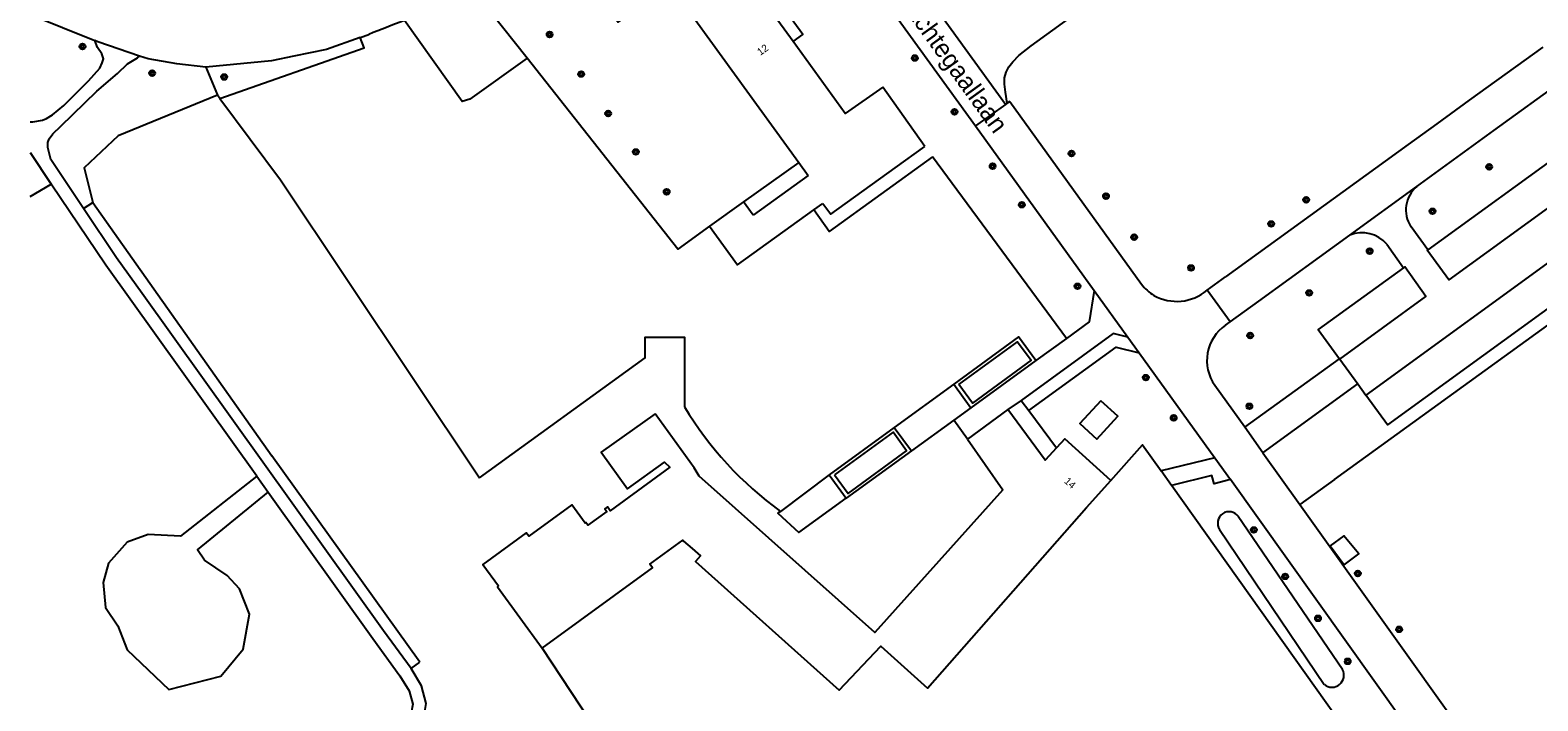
# Model space of a CAD drawing. Extents: x 141000 to 143000, y 400580 to 403500.
# Drawn here: x 141000 to 141206, y 402672.1 to 402763.7 of the extents above; entities that cross this region are included whole.
import ezdxf

# ---------------------------------------------------------------- set-up
doc = ezdxf.new("R2010")
doc.units = 0
for name, color, linetype in [('gg-afsc-erfafscheiding', 7, 'Continuous'), ('gg-afsc-hekwerk', 7, 'Continuous'), ('gg-anno-huisnummerreeks BGT', 7, 'Continuous'), ('gg-anno-openbare ruimte label', 7, 'Continuous'), ('gg-bbg-bijgebouw', 7, 'Continuous'), ('gg-bbg-gedigitaliseerde bebouwing', 7, 'Continuous'), ('gg-bbg-gedigitaliseerde bijgebouw', 7, 'Continuous'), ('gg-bbg-hoofdgebouw', 7, 'Continuous'), ('gg-bbg-luifel en loopbrug', 7, 'Continuous'), ('gg-knt-bronhoudergrens', 7, 'Continuous'), ('gg-knt-onverhard', 7, 'Continuous'), ('gg-knt-verharding', 7, 'Continuous'), ('gg-knt-verharding nz', 7, 'Continuous'), ('gg-kntw-bovenkant insteek waterloop', 7, 'Continuous'), ('gt-grn-groengrens', 7, 'Continuous'), ('gt-grn-vlakafsluiter', 7, 'Continuous'), ('gt-symb-boom', 7, 'Continuous')]:
    doc.layers.add(name, color=color, linetype=linetype)

# ---------------------------------------------------------------- blocks, each defined once
blk = doc.blocks.new('gt0-BOOM')
at = {"layer": 'gt-symb-boom'}
for radius in [0.4, 0.2]:
    blk.add_circle((0, 0), radius, dxfattribs=at)

msp = doc.modelspace()

# ---------------------------------------------------------------- linework, layer by layer
at = {"layer": 'gg-afsc-erfafscheiding'}
msp.add_line((141069.96, 402679.26), (141119.65, 402604.15), dxfattribs=at)
at = {"layer": 'gg-afsc-hekwerk'}
for p, q in [((141155.97, 402701.48), (141154.53, 402703.5)), ((141155.99, 402701.45), (141155.97, 402701.48)), ((141186.97, 402657.95), (141155.99, 402701.45))]:
    msp.add_line(p, q, dxfattribs=at)
for points in [[(141178.21, 402702.31), (141246.1, 402751.42), (141244.58, 402753.43), (141245.56, 402754.13)], [(141147.68, 402702.18), (141151.99, 402707.06), (141154.53, 402703.5)]]:
    msp.add_lwpolyline(points, dxfattribs=at)
at = {"layer": 'gg-bbg-bijgebouw'}
for points in [[(141126.9, 402715.28), (141134.93, 402721.12), (141136.77, 402718.61), (141128.74, 402712.76), (141126.9, 402715.28)], [(141109.91, 402702.95), (141111.76, 402700.41), (141119.75, 402706.25), (141117.91, 402708.78), (141109.91, 402702.95)]]:
    msp.add_lwpolyline(points, dxfattribs=at)
at = {"layer": 'gg-bbg-gedigitaliseerde bebouwing'}
for p, q in [((141106.31, 402743.86), (141098.77, 402738.44)), ((141098.77, 402738.44), (141097.47, 402740.25)), ((141107.08, 402739.15), (141108.33, 402740.05))]:
    msp.add_line(p, q, dxfattribs=at)
msp.add_lwpolyline([(141092.84, 402736.92), (141096.64, 402731.64), (141107.08, 402739.15)], dxfattribs=at)
at = {"layer": 'gg-bbg-gedigitaliseerde bijgebouw'}
msp.add_lwpolyline([(141146.28, 402713.08), (141143.43, 402709.95), (141145.76, 402707.84), (141148.6, 402710.97), (141146.28, 402713.08)], dxfattribs=at)
at = {"layer": 'gg-bbg-hoofdgebouw'}
for p, q in [((141104.26, 402762.16), (141102.16, 402765.06)), ((141122.26, 402747.82), (141116.49, 402755.94)), ((141105.01, 402745.66), (141106.31, 402743.86)), ((141097.47, 402740.25), (141092.84, 402736.92)), ((141133.61, 402711.86), (141128.08, 402707.81))]:
    msp.add_line(p, q, dxfattribs=at)
for points in [[(141094.34, 402786.54), (141087.86, 402781.83), (141087.17, 402782.8), (141083.74, 402780.37), (141084.44, 402779.39), (141077.98, 402774.71), (141078.38, 402774.14), (141075.24, 402771.85), (141076.6, 402769.97), (141078.13, 402767.86), (141079.19, 402766.4), (141080.35, 402764.8), (141083.95, 402767.4), (141087.45, 402769.93), (141105.01, 402745.66)], [(141116.49, 402755.94), (141111.38, 402752.32), (141104.26, 402762.16)], [(141108.33, 402740.05), (141109.39, 402738.57), (141118.18, 402744.93), (141122.26, 402747.82)], [(141085.4, 402711.3), (141078.02, 402706.04), (141081.64, 402701.04), (141086.66, 402704.67), (141087.39, 402703.98), (141079.24, 402698.05), (141078.87, 402698.56), (141078.53, 402698.31), (141078.78, 402697.96), (141076.18, 402696.08), (141075.94, 402696.42), (141075.84, 402696.36), (141074.02, 402698.85), (141068.16, 402694.56), (141067.79, 402695.01), (141061.86, 402690.69), (141064, 402687.76), (141063.86, 402687.66), (141069.96, 402679.26)], [(141128.08, 402707.81), (141132.9, 402700.9), (141115.43, 402681.4), (141091.43, 402702.77), (141090.71, 402703.91), (141085.4, 402711.3)], [(141140.23, 402706.64), (141138.68, 402704.95), (141133.61, 402711.86)], [(141147.68, 402702.18), (141141.37, 402707.88), (141140.23, 402706.64)], [(141089.28, 402693.89), (141090.45, 402692.87), (141091.6, 402691.86), (141090.93, 402691.1), (141110.52, 402673.53), (141116.22, 402679.53), (141122.61, 402673.8), (141144.32, 402698.48), (141147.68, 402702.18)], [(141069.96, 402679.26), (141085.02, 402690.22), (141084.66, 402690.72), (141089.17, 402694), (141089.28, 402693.89)]]:
    msp.add_lwpolyline(points, dxfattribs=at)
at = {"layer": 'gg-bbg-luifel en loopbrug'}
msp.add_line((141105.01, 402745.66), (141097.47, 402740.25), dxfattribs=at)
for points in [[(141104.26, 402762.16), (141105.58, 402763.12), (141103.48, 402766.02), (141102.16, 402765.06)], [(141179.56, 402690.66), (141181.55, 402692.15), (141179.5, 402694.62), (141177.64, 402693.23), (141179.56, 402690.66)]]:
    msp.add_lwpolyline(points, dxfattribs=at)
at = {"layer": 'gg-knt-bronhoudergrens'}
for p, q in [((141023.99, 402758.67), (141025.59, 402754.86)), ((141025.93, 402754.4), (141025.59, 402754.86)), ((141025.93, 402754.4), (141034.19, 402743.28)), ((141141.62, 402721.6), (141123.29, 402746.43)), ((141000, 402741.01), (141002.89, 402742.69)), ((141034.19, 402743.28), (141061.39, 402702.53))]:
    msp.add_line(p, q, dxfattribs=at)
for points in [[(141067.89, 402759.91), (141060.07, 402754.29), (141059.02, 402753.96), (141051.17, 402765.06)], [(141025.93, 402754.4), (141045.64, 402761.31), (141045.11, 402762.73)], [(141092.84, 402736.92), (141088.51, 402733.81), (141067.89, 402759.91)], [(141123.29, 402746.43), (141109.19, 402736.22), (141107.08, 402739.15)], [(141061.39, 402702.53), (141084.03, 402718.95), (141084.03, 402721.76), (141089.4, 402721.76), (141089.4, 402712.25)], [(141030.96, 402702.76), (141020.55, 402694.58), (141016.11, 402694.79), (141013.25, 402693.73), (141010.71, 402690.88), (141009.97, 402688.23), (141010.29, 402684.84), (141011.98, 402682.3), (141013.25, 402679.02), (141018.96, 402673.63), (141026.06, 402675.43), (141029.12, 402679.13), (141029.97, 402683.89), (141028.6, 402687.38), (141026.9, 402689.18), (141023.83, 402691.3), (141022.88, 402692.68), (141032.52, 402700.59)]]:
    msp.add_lwpolyline(points, dxfattribs=at)
msp.add_arc((141130.96, 402737.24), 48.49, 211.0203, 234.1, dxfattribs=at)
at = {"layer": 'gg-knt-onverhard'}
for p, q in [((141165.96, 402709.46), (141178.9, 402718.8)), ((141168.45, 402705.97), (141181.39, 402715.38))]:
    msp.add_line(p, q, dxfattribs=at)
at = {"layer": 'gg-knt-verharding'}
for p, q in [((141136.76, 402761.6), (141183.21, 402795.27)), ((141114.99, 402770.21), (141129.15, 402750.66)), ((141000, 402765.89), (141008.86, 402762.31)), ((141133.26, 402753.55), (141124.54, 402765.62)), ((141045.11, 402762.73), (141046.27, 402763.15)), ((141240.61, 402756.07), (141182.5, 402713.85)), ((141133.85, 402753.97), (141151.86, 402729.02)), ((141217.51, 402752.99), (141190.98, 402733.72)), ((141129.15, 402750.66), (141145.37, 402728.16)), ((141192.21, 402750.94), (141188.29, 402748.1)), ((141188.29, 402748.1), (141163.35, 402730.01)), ((141000, 402746.99), (141002.89, 402742.69)), ((141180.3, 402735.71), (141189.48, 402742.38)), ((141167.87, 402726.68), (141180.3, 402735.71)), ((141190.98, 402733.72), (141188.68, 402736.86)), ((141185.36, 402734.46), (141187.64, 402731.24)), ((141160.82, 402728.18), (141163.35, 402730.01)), ((141163.96, 402723.84), (141160.82, 402728.18)), ((141163.96, 402723.84), (141167.87, 402726.68)), ((141163.32, 402723.4), (141163.96, 402723.84)), ((141141.62, 402721.6), (141137.43, 402718.56)), ((141151.55, 402719.63), (141161.88, 402705.29)), ((141137.43, 402718.56), (141128.54, 402712.11)), ((141178.9, 402718.8), (141178.94, 402718.75)), ((141178.94, 402718.75), (141181.39, 402715.38)), ((141126.19, 402715.34), (141118.07, 402709.43)), ((141126.19, 402715.34), (141128.54, 402712.11)), ((141165.96, 402709.46), (141161.86, 402715.18)), ((141181.39, 402715.38), (141182.5, 402713.85)), ((141135.43, 402713.13), (141136.45, 402711.76)), ((141128.54, 402712.11), (141126.19, 402710.41)), ((141136.45, 402711.76), (141140.23, 402706.64)), ((141118.07, 402709.43), (141109.19, 402702.95)), ((141118.07, 402709.43), (141120.41, 402706.21)), ((141126.19, 402710.41), (141120.41, 402706.21)), ((141168.45, 402705.97), (141165.96, 402709.46)), ((141120.41, 402706.21), (141111.51, 402699.75)), ((141161.88, 402705.29), (141154.53, 402703.5)), ((141168.45, 402705.97), (141173.49, 402698.9)), ((141030.96, 402702.76), (141032.52, 402700.59)), ((141109.19, 402702.95), (141102.52, 402697.96)), ((141109.19, 402702.95), (141111.51, 402699.75))]:
    msp.add_line(p, q, dxfattribs=at)
for points in [[(141000, 402751.22), (141000.36, 402751.2), (141001.67, 402751.43), (141002.24, 402751.65), (141003.05, 402752.16), (141004.59, 402753.43), (141007.96, 402756.79), (141009.52, 402758.55), (141009.86, 402759.24), (141010.01, 402759.82), (141009.79, 402760.47), (141009.21, 402761.38), (141008.86, 402762.31)], [(141014.94, 402760.19), (141009.27, 402762.14), (141008.86, 402762.31)], [(141045.11, 402762.73), (141040.5, 402761.09), (141036.02, 402760.17), (141032.97, 402759.54), (141023.99, 402758.67)], [(141007.31, 402739.34), (141002.81, 402746.06), (141002.43, 402747.68), (141002.41, 402748.37), (141002.62, 402748.89), (141003.12, 402749.54), (141004.17, 402750.59), (141009.09, 402755.37), (141011.95, 402757.81), (141013.28, 402759.12), (141014.68, 402759.95), (141014.94, 402760.19)], [(141023.99, 402758.67), (141020.04, 402759.12), (141016.11, 402759.79), (141014.94, 402760.19)], [(141133.51, 402753.73), (141133.25, 402755.25), (141133.11, 402756.36), (141133.15, 402757.19), (141133.35, 402757.97), (141133.73, 402758.7), (141134.26, 402759.38), (141135.1, 402760.26), (141136.76, 402761.6)], [(141206.67, 402761.42), (141196.62, 402754.14), (141192.21, 402750.94)], [(141240.61, 402756.07), (141243.56, 402751.99), (141185.46, 402709.78), (141182.5, 402713.85)], [(141189.48, 402742.38), (141199.98, 402750), (141209.69, 402757.02)], [(141217.51, 402752.99), (141217.61, 402753.06), (141220.56, 402749.02), (141193.83, 402729.59), (141190.88, 402733.65), (141190.98, 402733.72)], [(141030.96, 402702.76), (141010.33, 402731.59), (141002.89, 402742.69)], [(141015.29, 402727.75), (141011.81, 402732.61), (141007.31, 402739.34)], [(141178.94, 402718.75), (141190.72, 402727.31), (141187.85, 402731.38), (141187.64, 402731.24)], [(141187.64, 402731.24), (141175.99, 402722.83), (141178.9, 402718.8)], [(141052.04, 402676.48), (141048.29, 402681.63), (141015.29, 402727.75)], [(141145.37, 402728.16), (141144.71, 402723.85), (141141.62, 402721.6)], [(141137.43, 402718.56), (141135.04, 402721.83), (141126.19, 402715.34)], [(141149.98, 402721.76), (141147.98, 402722.27), (141135.43, 402713.13)], [(141136.45, 402711.76), (141148.38, 402720.42), (141151.55, 402719.63)], [(141164.02, 402702.3), (141161.78, 402701.74), (141161.46, 402702.88), (141155.97, 402701.48)], [(141032.52, 402700.59), (141046.83, 402680.58), (141050.53, 402675.49), (141051.78, 402673.41), (141052.27, 402671.62), (141052.05, 402670.43), (141051.7, 402668.92), (141050.58, 402667.46), (141042.53, 402661.46), (141028.12, 402651.12)], [(141191.75, 402661.36), (141190.58, 402663.11), (141191.51, 402663.73), (141164.02, 402702.3)], [(141102.52, 402697.96), (141102.16, 402697.69), (141105.05, 402695.06), (141111.51, 402699.75)], [(141173.49, 402698.9), (141196.21, 402667.07), (141197.22, 402667.79), (141198.44, 402666.08)], [(141033.63, 402652.84), (141043.59, 402660.01), (141051.85, 402666.16), (141053.37, 402668.13), (141053.82, 402670.07), (141054.11, 402671.7), (141053.45, 402674.13), (141052.04, 402676.48)]]:
    msp.add_lwpolyline(points, dxfattribs=at)
for centre, radius, start, end in [((141236.9, 402281.83), 517.7, 111.0249, 111.607), ((141192.17, 402739.17), 4.19, 129.9608, 213.3864), ((141181.98, 402731.62), 4.42, 40.0515, 112.3188), ((141156.51, 402732.41), 5.75, 216.0582, 238.9763), ((141156.68, 402733.04), 6.38, 240.5661, 310.3666), ((141166.67, 402718.57), 5.88, 124.7659, 215.1108)]:
    msp.add_arc(centre, radius, start, end, dxfattribs=at)
at = {"layer": 'gg-knt-verharding nz'}
for p, q in [((141145.37, 402728.16), (141149.98, 402721.76)), ((141149.98, 402721.76), (141151.55, 402719.63)), ((141135.43, 402713.13), (141133.61, 402711.86)), ((141161.88, 402705.29), (141164.02, 402702.3))]:
    msp.add_line(p, q, dxfattribs=at)
at = {"layer": 'gg-kntw-bovenkant insteek waterloop'}
for p, q in [((141179.32, 402676.34), (141165.08, 402697.27)), ((141162.53, 402695.48), (141176.83, 402674.28))]:
    msp.add_line(p, q, dxfattribs=at)
for centre, radius, start, end in [((141163.83, 402696.35), 1.56, 36.2916, 213.7316), ((141177.87, 402675.57), 1.65, 231.1835, 27.8919)]:
    msp.add_arc(centre, radius, start, end, dxfattribs=at)
at = {"layer": 'gt-grn-groengrens'}
for p, q in [((141007.31, 402739.34), (141008.56, 402740.17)), ((141008.56, 402740.17), (141033.01, 402705.56)), ((141053.25, 402677.36), (141033.01, 402705.56)), ((141052.04, 402676.48), (141053.25, 402677.36))]:
    msp.add_line(p, q, dxfattribs=at)
msp.add_lwpolyline([(141025.59, 402754.86), (141012.04, 402749.29), (141007.39, 402744.91), (141008.56, 402740.17)], dxfattribs=at)
at = {"layer": 'gt-grn-vlakafsluiter'}
for p, q in [((141067.89, 402759.91), (141060.23, 402769.6)), ((141133.26, 402753.55), (141129.15, 402750.66)), ((141133.51, 402753.73), (141133.26, 402753.55)), ((141133.85, 402753.97), (141133.51, 402753.73)), ((141128.08, 402707.81), (141126.19, 402710.41)), ((141178.21, 402702.31), (141173.49, 402698.9))]:
    msp.add_line(p, q, dxfattribs=at)

# ---------------------------------------------------------------- block references
at = {"layer": 'gt-symb-boom'}
for p in [(141070.98, 402763.14), (141007.15, 402761.5), (141120.89, 402759.92), (141016.67, 402757.85), (141075.3, 402757.73), (141026.5, 402757.33), (141078.97, 402752.34), (141126.3, 402752.56), (141082.76, 402747.08), (141142.28, 402746.88), (141131.51, 402745.13), (141199.35, 402745.05), (141086.97, 402741.64), (141135.51, 402739.87), (141147, 402741.05), (141174.34, 402740.53), (141169.57, 402737.24), (141191.6, 402738.97), (141150.86, 402735.44), (141183.03, 402733.53), (141158.62, 402731.23), (141143.11, 402728.72), (141174.76, 402727.81), (141166.7, 402722), (141152.45, 402716.24), (141156.25, 402710.73), (141166.59, 402712.32), (141167.19, 402695.42), (141171.48, 402689.07), (141181.42, 402689.46), (141175.97, 402683.34), (141187.07, 402681.83), (141180.03, 402677.46)]:
    msp.add_blockref('gt0-BOOM', p, dxfattribs=at)

# ---------------------------------------------------------------- texts
at = {"layer": 'gg-anno-huisnummerreeks BGT'}
for s, rotation, p in [('12', 35.9, (141099.78, 402760.21)), ('14', 317.9, (141141.21, 402701.96))]:
    msp.add_text(s, height=1, rotation=rotation, dxfattribs=at).set_placement(p)
at = {"layer": 'gg-anno-openbare ruimte label'}
msp.add_text('Nachtegaallaan', height=2.5, rotation=305.8, dxfattribs=at).set_placement((141118.15, 402768.26))

doc.saveas('drawing.dxf')
